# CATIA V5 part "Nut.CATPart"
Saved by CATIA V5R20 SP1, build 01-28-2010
Part number: nut
Bounding box of the stored display mesh (mm): x -13.856 to 13.856, y 0 to 9, z -12 to 12
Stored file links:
  D:\v5_r20\psrt_files_downloaded\c14\c14-catia-v5r20-figr-14-26 & 27\Part & Asm\Nut.CATPart
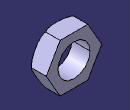
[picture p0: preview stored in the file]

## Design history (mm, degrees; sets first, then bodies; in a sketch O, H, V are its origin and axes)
Body1 (main body)
  Sketch1 on zx-plane, origin (0, 0, 0), H (-1, 0, 0), V (0, 0, 1)
    circle A1 centre (0, 0) radius 8
    construction circle A2 centre (0, 0) radius 12
    point P1 (-6.9282, -12)
    point P2 (6.9282, -12)
    point P3 (13.8564, 0)
    point P4 (6.9282, 12)
    point P5 (-6.9282, 12)
    point P6 (-13.8564, 0)
    point P7 (0, -12)
    line L1 (-6.9282, -12) -> (6.9282, -12)
    line L2 (6.9282, -12) -> (13.8564, 0)
    line L3 (13.8564, 0) -> (6.9282, 12)
    line L4 (6.9282, 12) -> (-6.9282, 12)
    line L5 (-6.9282, 12) -> (-13.8564, 0)
    line L6 (-13.8564, 0) -> (-6.9282, -12)
    construction line L7 (0, 0) -> (0, -12)
    construction circle A3 centre (0, 0) radius 13.8564
    construction arc A4 centre (-6.9282, 12) radius 13.8564 from (6.9282, 12) to (-13.8564, 0) cw
    construction arc A5 centre (6.9282, -12) radius 13.8564 from (13.8564, 0) to (-6.9282, -12) ccw
    radius A1 = 8
    radius A2 = 12
    coincidence: P7 A2, A3 P1, A3 P2, A3 P3, A3 P4, A3 P5, A3 P6, A4 O, A5 O
    vertical: L7 V
    midpoint: P7 L1
    parallelism: L1 L4
  Pad1: profile Sketch1, direction (0, 1, 0), length 9
  Sketch2 on xy-plane, origin (0, 0, 0), H (1, 0, 0), V (0, 1, 0)
    projected line E1 (10.7061, 0) -> (13.8564, 0) from edge of Pad1
    point P1 (13.8564, 0)
    projected line E2 (13.8564, 0) -> (13.8564, 1.8188) from edge of Pad1
    point P2 (13.8564, 0)
    arc A1 centre (10.7061, 3.6376) radius 3.6376 from (10.7061, 0) to (13.8564, 1.8188) ccw
    coincidence: P1 P2
    tangency: A1 E1
  Groove1: profile Sketch2, axis axis of face of Pad1, angle 360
